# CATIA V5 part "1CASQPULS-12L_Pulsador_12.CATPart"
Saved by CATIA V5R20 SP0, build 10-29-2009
Part number: 1CASQPULS-12L_Pulsador_12
Revision: ANY
Definition: UNKNOWN
Nomenclature: 1CASQPULS-12L_Pulsador_12
Source: Unknown
Bounding box of the stored display mesh (mm): x -9.8 to 9.8, y 0 to 14.3, z -9.8 to 9.8
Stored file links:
  C:\Users\Utente\Desktop\IO LAVORO\3D X SITO CF\CUMSA\3D files AE\1CASQPULS-12L_Pulsador_12.CATPart
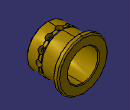
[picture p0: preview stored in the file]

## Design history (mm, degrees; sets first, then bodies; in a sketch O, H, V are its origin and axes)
Body1 "MatrizC1" (main body)
  Solid1: solid without history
